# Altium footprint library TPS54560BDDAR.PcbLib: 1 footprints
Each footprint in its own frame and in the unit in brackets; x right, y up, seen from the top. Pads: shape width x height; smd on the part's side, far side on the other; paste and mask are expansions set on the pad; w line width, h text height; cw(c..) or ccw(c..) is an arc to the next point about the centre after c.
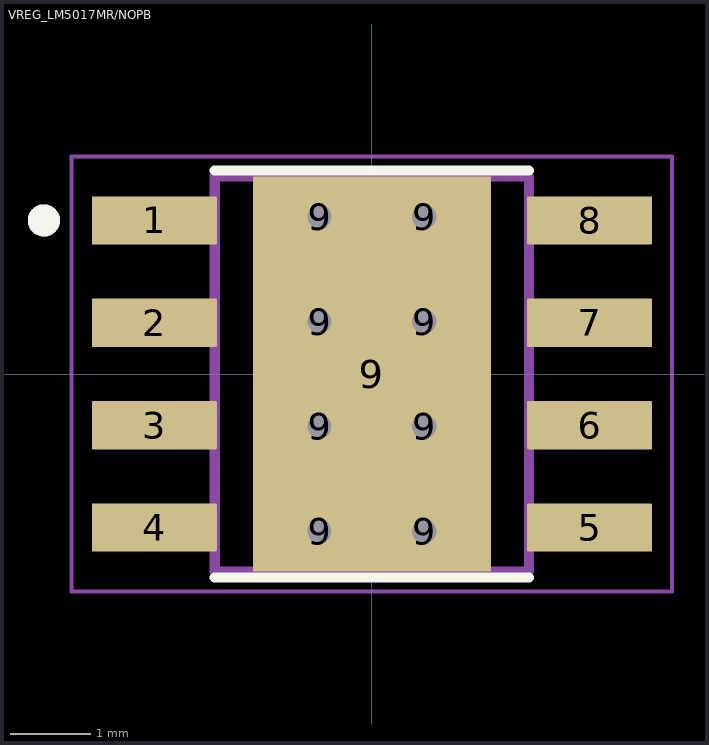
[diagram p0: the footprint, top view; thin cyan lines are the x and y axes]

## VREG_LM5017MR/NOPB [mm]
pads (17):
  rrect5% 1.55x0.6 smd mask+0: 1(-2.7,1.905) 2(-2.7,0.635) 3(-2.7,-0.635) 4(-2.7,-1.905) 5(2.7,-1.905) 6(2.7,-0.635) 7(2.7,0.635) 8(2.7,1.905)
  round 0.6 hole 0.3: 9(-0.65,-1.95) 9(-0.65,-0.65) 9(-0.65,0.65) 9(-0.65,1.95) 9(0.65,-1.95) 9(0.65,-0.65) 9(0.65,0.65) 9(0.65,1.95)
  rect 2.95x4.9 smd paste-3 mask+0: 9(0,0)
Top Overlay:
  circle w0.2: c-4.07,1.905 r0.1
  lines w0.127: -1.95,-2.525 1.95,-2.525 ; -1.95,2.525 1.95,2.525
Top Paste:
  region: 1.355,-1.7 -1.355,-1.7 -1.355,1.7 1.355,1.7
Top Solder:
  drawing of 9 lines, arcs and shapes, not listed
Assembly Top:
  circle w0.2: c-4.07,1.905 r0.1
  lines w0.127: -1.95,-2.45 -1.95,2.45 1.95,2.45 1.95,-2.45 -1.95,-2.45
Courtyard Top:
  lines w0.05: -3.725,-2.7 -3.725,2.7 3.725,2.7 3.725,-2.7 -3.725,-2.7
3D body "step_temp.STEP": height 1.7, standoff 0, extent -3,-2.45 3,2.45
